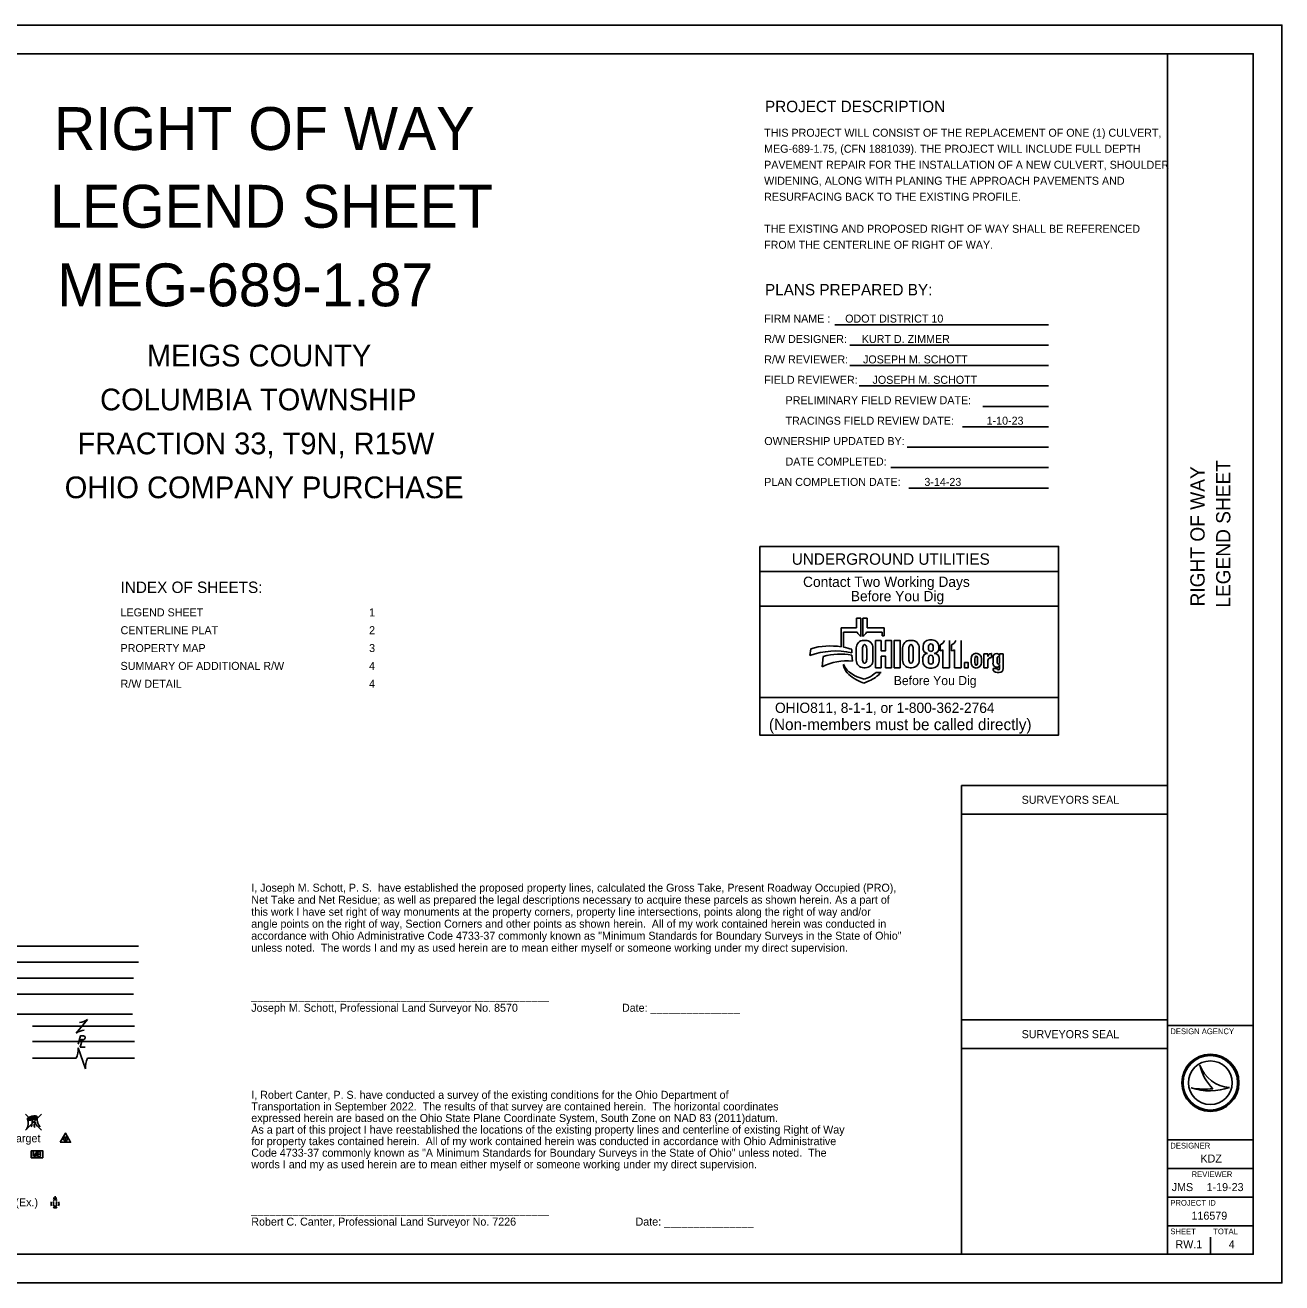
# Model space of a CAD drawing. Extents: x 0 to 34, y 0 to 22.
# Drawn here: x 12.02 to 34, y 0 to 22 of the extents above; entities that cross this region are included whole.
import ezdxf

# ---------------------------------------------------------------- set-up
doc = ezdxf.new("R2010")
doc.units = 0
for name, color, linetype in [('SH_Border', 7, 'Continuous'), ('SH_Cut_Line', 7, 'Continuous'), ('SH_Data', 7, 'Continuous'), ('SH_Text', 7, 'Continuous')]:
    doc.layers.add(name, color=color, linetype=linetype)

msp = doc.modelspace()

# ---------------------------------------------------------------- linework, layer by layer
at = {"layer": 'SH_Border'}
for p, q in [((32, 0.5), (32, 21.5)), ((32, 4.5), (33.5, 4.5)), ((32, 2.5), (33.5, 2.5)), ((32, 2), (33.5, 2)), ((32, 1.5), (33.5, 1.5)), ((32, 1), (33.5, 1))]:
    msp.add_line(p, q, dxfattribs=at)
msp.add_lwpolyline([(1.5, 21.5), (33.5, 21.5), (33.5, 0.5), (1.5, 0.5)], close=True, dxfattribs=at)
at = {"layer": 'SH_Cut_Line'}
msp.add_lwpolyline([(0, 0), (34, 0), (34, 22), (0, 22)], close=True, dxfattribs=at)
at = {"layer": 'SH_Data'}
for p, q in [((26.559, 11.46), (26.296, 11.46)), ((26.296, 11.46), (26.296, 11.125)), ((26.639, 11.626), (26.559, 11.626)), ((26.559, 11.626), (26.559, 11.46)), ((26.639, 11.309), (26.639, 11.626)), ((26.75, 11.626), (26.67, 11.626)), ((26.67, 11.626), (26.67, 11.309)), ((26.75, 11.46), (26.75, 11.626)), ((27.048, 11.46), (26.75, 11.46)), ((27.048, 11.319), (27.048, 11.46)), ((26.334, 11.119), (26.334, 11.383)), ((26.334, 11.383), (26.574, 11.383)), ((26.716, 11.238), (26.691, 11.238)), ((26.735, 11.383), (27.013, 11.383)), ((26.993, 11.237), (26.892, 11.237)), ((26.892, 11.237), (26.892, 10.759)), ((27.013, 11.383), (27.013, 11.319)), ((27.013, 11.319), (27.048, 11.319)), ((27.526, 11.238), (27.502, 11.238)), ((27.887, 11.245), (27.839, 11.245)), ((28.191, 11.237), (28.191, 10.759)), ((28.391, 11.237), (28.391, 10.759)), ((25.761, 11.091), (25.747, 10.974)), ((26.48, 11.023), (26.48, 11.081)), ((26.557, 11.105), (26.557, 10.893)), ((26.666, 10.91), (26.666, 11.092)), ((26.741, 11.092), (26.741, 10.91)), ((26.849, 10.893), (26.849, 11.105)), ((27.368, 11.105), (27.368, 10.893)), ((27.477, 10.91), (27.477, 11.092)), ((27.551, 11.092), (27.551, 10.91)), ((27.66, 10.893), (27.66, 11.105)), ((27.725, 11.131), (27.725, 11.095)), ((27.823, 11.078), (27.823, 11.136)), ((27.904, 11.136), (27.904, 11.078)), ((28.001, 11.095), (28.001, 11.131)), ((28.024, 11.057), (28.024, 11.158)), ((28.073, 10.759), (28.073, 11.071)), ((28.225, 11.057), (28.225, 11.158)), ((28.273, 10.759), (28.273, 11.071)), ((28.86, 11.002), (28.787, 11.002)), ((28.787, 11.002), (28.787, 10.759)), ((28.86, 10.955), (28.86, 11.002)), ((28.921, 11.01), (28.915, 11.01)), ((28.921, 10.936), (28.921, 11.01)), ((29.064, 10.957), (29.064, 11.004)), ((29.064, 11.004), (29.129, 11.004)), ((29.129, 11.004), (29.129, 10.745)), ((25.981, 10.956), (25.959, 10.776)), ((26.333, 10.819), (26.337, 10.792)), ((26.49, 10.873), (26.481, 10.979)), ((26.993, 10.759), (26.993, 10.961)), ((27.719, 10.925), (27.719, 10.874)), ((27.82, 10.865), (27.82, 10.926)), ((27.905, 10.926), (27.905, 10.865)), ((28.007, 10.874), (28.007, 10.925)), ((28.565, 10.85), (28.565, 10.918)), ((28.632, 10.849), (28.632, 10.918)), ((28.68, 10.918), (28.68, 10.849)), ((28.748, 10.918), (28.748, 10.85)), ((28.86, 10.759), (28.86, 10.886)), ((28.909, 10.936), (28.921, 10.936)), ((28.949, 10.837), (28.949, 10.941)), ((29.021, 10.851), (29.021, 10.927)), ((29.064, 10.927), (29.064, 10.851)), ((29.064, 10.745), (29.064, 10.815)), ((26.698, 10.558), (26.609, 10.589)), ((26.691, 10.759), (26.716, 10.759)), ((26.759, 10.585), (26.698, 10.558)), ((26.892, 10.759), (26.993, 10.759)), ((26.991, 10.679), (26.905, 10.679)), ((26.989, 10.676), (26.991, 10.679)), ((27.502, 10.759), (27.526, 10.759)), ((27.84, 10.753), (27.887, 10.753)), ((28.191, 10.759), (28.073, 10.759)), ((28.391, 10.759), (28.273, 10.759)), ((28.787, 10.759), (28.86, 10.759)), ((28.949, 10.745), (29.021, 10.745)), ((29.059, 10.676), (29.019, 10.676)), ((26.633, 10.512), (26.689, 10.488)), ((26.689, 10.488), (26.783, 10.529)), ((30.095, 9.581), (24.87, 9.581)), ((28.4, 8.2), (32, 8.2)), ((28.4, 4.1), (32, 4.1)), ((32.567, 3.81), (32.567, 3.81)), ((32.417, 3.41), (32.417, 3.41)), ((32.75, 3.5), (32.75, 3.5)), ((33.087, 3.419), (33.087, 3.419)), ((32.375, 0.675), (32.375, 0.675)), ((32.75, 0.5), (32.75, 0.8))]:
    msp.add_line(p, q, dxfattribs=at)
for points in [[(24.87, 12.881), (30.095, 12.881), (30.095, 12.441), (24.87, 12.441)], [(24.87, 12.441), (30.095, 12.441), (30.095, 11.836), (24.87, 11.836)], [(24.87, 11.836), (30.095, 11.836), (30.095, 10.241), (24.87, 10.241)], [(28.449, 10.849), (28.515, 10.849), (28.515, 10.759), (28.449, 10.759)], [(24.87, 10.241), (30.095, 10.241), (30.095, 9.581), (24.87, 9.581)], [(28.4, 8.7), (32, 8.7), (32, 4.6), (28.4, 4.6)], [(28.4, 4.6), (32, 4.6), (32, 0.5), (28.4, 0.5)]]:
    msp.add_lwpolyline(points, close=True, dxfattribs=at)
for points in [[(26.993, 10.961), (27.07, 10.961), (27.07, 10.759), (27.171, 10.759), (27.171, 11.237), (27.07, 11.237), (27.07, 11.057), (26.993, 11.057), (26.993, 11.237)], [(27.222, 10.759), (27.325, 10.759), (27.325, 11.237), (27.222, 11.237), (27.222, 10.759)], [(27.805, 11.011), (27.805, 11.011)], [(27.921, 11.011), (27.921, 11.011)]]:
    msp.add_lwpolyline(points, dxfattribs=at)
for radius in [0.5, 0.477, 0.477, 0.382]:
    msp.add_circle((32.75, 3.5), radius, dxfattribs=at)
for centre, radius, start, end in [((26.691, 11.105), 0.134, 90, 180), ((26.711, 11.438), 0.147, 201.9296, 240.7469), ((26.598, 11.438), 0.147, 299.2531, 338.0704), ((26.716, 11.105), 0.134, 0, 90), ((27.502, 11.105), 0.134, 90, 180), ((27.526, 11.105), 0.134, 0, 90), ((27.839, 11.131), 0.114, 90, 180), ((27.887, 11.131), 0.114, 0, 90), ((27.974, 11.281), 0.132, 292.5572, 340.7355), ((28.174, 11.281), 0.132, 292.5572, 340.7355), ((26.199, 9.721), 1.332, 77.8238, 109.8274), ((26.105, 9.917), 1.224, 81.0007, 106.3144), ((26.105, 9.917), 1.224, 72.1402, 79.2074), ((27.805, 10.925), 0.0865, 90, 180), ((27.808, 11.095), 0.0837, 180, 268.1442), ((27.918, 11.095), 0.0837, 272.2058, 0), ((27.921, 10.925), 0.0865, 0, 90), ((28.013, 11.188), 0.132, 275.1733, 297.0931), ((28.213, 11.188), 0.132, 275.1733, 297.0931), ((28.661, 10.918), 0.0956, 92.5886, 180), ((28.652, 10.918), 0.0956, 0, 87.4114), ((28.915, 10.955), 0.0548, 90, 180), ((29.018, 10.941), 0.0686, 92.6865, 180), ((29.012, 10.957), 0.0524, 0, 86.9262), ((26.388, 9.929), 0.95, 83.8248, 116.8021), ((26.28, 9.904), 1.094, 79.44, 105.8467), ((26.613, 10.927), 0.3, 201.0457, 232.5314), ((26.548, 10.828), 0.214, 189.6817, 216.0884), ((26.691, 10.893), 0.134, 180, 270), ((26.716, 10.893), 0.134, 270, 0), ((27.502, 10.893), 0.134, 180, 270), ((27.526, 10.893), 0.134, 270, 0), ((27.84, 10.874), 0.121, 180, 270), ((27.887, 10.874), 0.121, 270, 0), ((28.661, 10.85), 0.0956, 180, 267.4114), ((28.652, 10.85), 0.0956, 272.5886, 0), ((28.909, 10.886), 0.0493, 90, 180), ((29.018, 10.837), 0.0692, 180, 265.7132), ((29.017, 10.815), 0.0467, 264.7825, 0), ((26.748, 10.974), 0.461, 216.0884, 235.7167), ((26.9, 11.302), 0.773, 232.5314, 241.794), ((26.997, 11.339), 0.903, 235.7167, 246.2325), ((26.773, 11.065), 0.504, 241.794, 250.9821), ((26.545, 11.078), 0.538, 293.4582, 312.0712), ((26.545, 11.078), 0.599, 293.4582, 317.8286), ((29.019, 10.745), 0.0699, 180, 270), ((29.059, 10.745), 0.0699, 270, 0), ((33.116, 3.998), 0.58, 198.9257, 198.9319), ((33.347, 3.97), 0.796, 191.6379, 191.6421), ((33.116, 3.998), 0.58, 198.9319, 267.1657), ((33.347, 3.97), 0.796, 191.6421, 226.0947), ((32.739, 4.37), 1.013, 251.4576, 290.0832), ((32.648, 4.654), 1.266, 259.4964, 259.4995), ((32.739, 4.37), 1.013, 251.4527, 251.4576), ((32.648, 4.654), 1.266, 259.4995, 276.6672)]:
    msp.add_arc(centre, radius, start, end, dxfattribs=at)
for centre, major_axis, ratio, start_param, end_param in [((26.703, 11.092), (0, 0.0723), 0.514403, 4.712389, 7.853982), ((27.514, 11.092), (0, 0.0723), 0.514403, 4.712389, 7.853982), ((27.864, 11.136), (0.0404, 0), 0.969373, 0, 3.141593), ((27.864, 11.078), (0.0404, 0), 0.818453, 3.141593, 6.283185), ((26.703, 10.91), (0, 0.0723), 0.514403, 1.570796, 4.712389), ((27.514, 10.91), (0, 0.0723), 0.514403, 1.570796, 4.712389), ((27.862, 10.926), (0, 0.0535), 0.794529, 4.712389, 7.853982), ((27.862, 10.865), (0.0425, 0), 0.959837, 3.141593, 6.283185), ((28.656, 10.918), (0, 0.0434), 0.553236, 4.712389, 7.853982), ((28.656, 10.849), (0, 0.046), 0.522014, 1.570796, 4.712389), ((29.043, 10.927), (0, 0.0275), 0.777179, 4.712389, 7.853982), ((29.043, 10.851), (0, 0.0275), 0.777179, 1.570796, 4.712389), ((29.043, 10.745), (0.0214, 0), 0.959012, 3.141593, 6.283185)]:
    msp.add_ellipse(centre, major_axis=major_axis, ratio=ratio, start_param=start_param, end_param=end_param, dxfattribs=at)
at = {"layer": 'SH_Text'}
for p, q in [((26.181, 16.76), (29.918, 16.76)), ((26.445, 16.403), (29.918, 16.403)), ((26.445, 16.046), (29.918, 16.046)), ((26.609, 15.689), (29.918, 15.689)), ((28.773, 15.331), (29.918, 15.331)), ((28.415, 14.974), (29.918, 14.974)), ((27.445, 14.617), (29.918, 14.617)), ((27.16, 14.26), (29.918, 14.26)), ((27.475, 13.903), (29.918, 13.903)), ((10.521, 5.889), (14.004, 5.889)), ((10.521, 5.609), (14.004, 5.609)), ((10.02, 5.329), (13.92, 5.329)), ((10.02, 5.049), (13.92, 5.049)), ((9.553, 4.699), (13.903, 4.698)), ((12.151, 4.489), (13.933, 4.489)), ((12.916, 4.369), (13.116, 4.609)), ((13.016, 4.489), (13.016, 4.489)), ((12.151, 4.224), (13.933, 4.224)), ((12.974, 4.253), (13.039, 4.253)), ((13.014, 4.222), (13.014, 4.222)), ((12.951, 4.113), (13.081, 3.744)), ((12.151, 3.929), (12.916, 3.929)), ((13.016, 3.929), (13.016, 3.929)), ((13.116, 3.929), (13.933, 3.929)), ((12.029, 2.948), (12.307, 2.669)), ((12.307, 2.948), (12.029, 2.669)), ((12.168, 2.809), (12.168, 2.809)), ((12.168, 2.809), (12.168, 2.809)), ((12.23, 2.249), (12.23, 2.249)), ((12.579, 1.484), (12.515, 1.484)), ((12.52, 1.425), (12.52, 1.356)), ((12.547, 1.452), (12.547, 1.516)), ((12.547, 1.382), (12.547, 1.382)), ((12.574, 1.425), (12.574, 1.356))]:
    msp.add_line(p, q, dxfattribs=at)
for points in [[(12.953, 4.174), (12.992, 4.322), (13.043, 4.322)], [(13.027, 4.27), (12.988, 4.122), (13.075, 4.122)], [(12.165, 2.209), (12.165, 2.289), (12.194, 2.209), (12.221, 2.289), (12.221, 2.209)], [(12.281, 2.252), (12.284, 2.255), (12.286, 2.257), (12.287, 2.259), (12.288, 2.26), (12.289, 2.263), (12.289, 2.265), (12.291, 2.269), (12.291, 2.271), (12.291, 2.273), (12.29, 2.277), (12.289, 2.28), (12.287, 2.283), (12.284, 2.285), (12.281, 2.287), (12.28, 2.287), (12.277, 2.289), (12.246, 2.289), (12.246, 2.209), (12.281, 2.209), (12.285, 2.211), (12.289, 2.214), (12.292, 2.219), (12.294, 2.225), (12.295, 2.231), (12.295, 2.234), (12.293, 2.238), (12.291, 2.244), (12.288, 2.248), (12.281, 2.252), (12.246, 2.252)]]:
    msp.add_lwpolyline(points, dxfattribs=at)
for points in [[(12.638, 2.459), (12.818, 2.459), (12.728, 2.62)], [(12.13, 2.31), (12.33, 2.31), (12.33, 2.187), (12.13, 2.187)]]:
    msp.add_lwpolyline(points, close=True, dxfattribs=at)
for radius in [0.035, 0.008]:
    msp.add_circle((12.728, 2.516), radius, dxfattribs=at)
for centre, radius, start, end in [((13.074, 4.154), 0.267, 93.6945, 126.337), ((12.958, 4.823), 0.267, 273.6945, 306.337), ((13.038, 4.288), 0.0345, 270.471, 81.3281), ((12.619, 4.08), 0.334, 332.9422, 5.5848), ((13.413, 3.777), 0.334, 152.9422, 185.5848), ((11.877, 2.791), 0.2, 331.5338, 20.9269), ((12.449, 2.866), 0.215, 171.4106, 219.9194), ((11.892, 2.81), 0.253, 340.7938, 3.5481), ((12.364, 2.769), 0.182, 178.7926, 197.1224), ((12.494, 2.911), 0.316, 194.9653, 212.1216), ((12.547, 1.382), 0.07, 150.0184, 209.9816), ((12.547, 1.382), 0.07, 60.0184, 120.0157), ((12.547, 1.382), 0.07, 239.9843, 299.9816), ((12.547, 1.369), 0.03, 205.1924, 334.8076), ((12.547, 1.382), 0.07, 330.0184, 29.9816)]:
    msp.add_arc(centre, radius, start, end, dxfattribs=at)
for major_axis in [(0.0868, 0.0187), (0.0651, 0.0141), (0.0488, 0.0105), (0.0275, 0.0059), (0.0154, 0.0033)]:
    msp.add_ellipse((12.15, 2.884), major_axis=major_axis, ratio=0.36865, dxfattribs=at)

# ---------------------------------------------------------------- texts
at = {"layer": 'SH_Data'}
for s, height, p in [('RIGHT OF WAY', 0.75, (12.527, 19.816)), ('LEGEND SHEET', 0.75, (12.458, 18.457)), ('MEG-689-1.87', 0.75, (12.583, 17.082)), ('MEIGS COUNTY', 0.38, (14.152, 16.03)), ('COLUMBIA TOWNSHIP', 0.38, (13.334, 15.262)), ('FRACTION 33, T9N, R15W', 0.38, (12.94, 14.493)), ('OHIO COMPANY PURCHASE', 0.38, (12.715, 13.725)), ('UNDERGROUND UTILITIES', 0.2, (25.43, 12.561)), ('Contact Two Working Days', 0.18, (25.627, 12.173)), ('INDEX OF SHEETS:', 0.2, (13.692, 12.067)), ('Before You Dig', 0.18, (26.462, 11.923)), ('LEGEND SHEET', 0.14, (13.692, 11.658)), ('1', 0.14, (18.038, 11.658)), ('CENTERLINE PLAT', 0.14, (13.692, 11.346)), ('2', 0.14, (18.038, 11.346)), ('PROPERTY MAP', 0.14, (13.692, 11.034)), ('3', 0.14, (18.038, 11.034)), ('SUMMARY OF ADDITIONAL R/W', 0.14, (13.692, 10.722)), ('4', 0.14, (18.038, 10.722)), ('Before You Dig', 0.15972, (27.213, 10.456)), ('R/W DETAIL', 0.14, (13.692, 10.41)), ('4', 0.14, (18.038, 10.41)), ('OHIO811, 8-1-1, or 1-800-362-2764', 0.18, (25.136, 9.969)), ('(Non-members must be called directly)', 0.2, (25.03, 9.668)), ('SURVEYORS SEAL', 0.14, (29.45, 8.38)), ('SURVEYORS SEAL', 0.14, (29.45, 4.28)), ('DESIGN AGENCY', 0.1, (32.05, 4.35)), ('DESIGNER', 0.1, (32.05, 2.35)), ('KDZ', 0.14, (32.577, 2.105)), ('REVIEWER', 0.1, (32.422, 1.85)), ('JMS', 0.14, (32.074, 1.605)), ('1-19-23', 0.14, (32.685, 1.605)), ('PROJECT ID', 0.1, (32.05, 1.35)), ('116579', 0.14, (32.42, 1.105)), ('SHEET', 0.1, (32.05, 0.85)), ('TOTAL', 0.1, (32.8, 0.85)), ('RW.1', 0.14, (32.14, 0.605)), ('4', 0.14, (33.072, 0.605))]:
    msp.add_text(s, height=height, dxfattribs=at).set_placement(p)
for s, p in [('LEGEND SHEET', (33.1, 11.81)), ('RIGHT OF WAY', (32.65, 11.832))]:
    msp.add_text(s, height=0.25, rotation=90, dxfattribs=at).set_placement(p)
at = {"layer": 'SH_Text'}
for s, height, p in [('PROJECT DESCRIPTION', 0.2, (24.961, 20.478)), ('THIS PROJECT WILL CONSIST OF THE REPLACEMENT OF ONE (1) CULVERT, ', 0.14, (24.946, 20.048)), ('MEG-689-1.75, (CFN 1881039). THE PROJECT WILL INCLUDE FULL DEPTH ', 0.14, (24.946, 19.768)), ('PAVEMENT REPAIR FOR THE INSTALLATION OF A NEW CULVERT, SHOULDER ', 0.14, (24.946, 19.488)), ('WIDENING, ALONG WITH PLANING THE APPROACH PAVEMENTS AND ', 0.14, (24.946, 19.208)), ('RESURFACING BACK TO THE EXISTING PROFILE.', 0.14, (24.946, 18.928)), ('THE EXISTING AND PROPOSED RIGHT OF WAY SHALL BE REFERENCED ', 0.14, (24.946, 18.368)), ('FROM THE CENTERLINE OF RIGHT OF WAY.', 0.14, (24.946, 18.088)), ('PLANS PREPARED BY:', 0.2, (24.961, 17.273)), ('FIRM NAME :     ODOT DISTRICT 10', 0.14, (24.949, 16.797)), ('R/W DESIGNER:     KURT D. ZIMMER', 0.14, (24.949, 16.44)), ('R/W REVIEWER:     JOSEPH M. SCHOTT', 0.14, (24.949, 16.083)), ('FIELD REVIEWER:     JOSEPH M. SCHOTT', 0.14, (24.949, 15.726)), ('PRELIMINARY FIELD REVIEW DATE:', 0.14, (25.321, 15.369)), ('TRACINGS FIELD REVIEW DATE:           1-10-23', 0.14, (25.321, 15.011)), ('OWNERSHIP UPDATED BY:', 0.14, (24.949, 14.655)), ('DATE COMPLETED:', 0.14, (25.321, 14.297)), ('PLAN COMPLETION DATE:', 0.14, (24.949, 13.94)), ('3-14-23', 0.14, (27.749, 13.94)), ('I, Joseph M. Schott, P. S.  have established the proposed property lines, calculated the Gross Take, Present Roadway Occupied (PRO),', 0.14, (15.978, 6.842)), ('Net Take and Net Residue; as well as prepared the legal descriptions necessary to acquire these parcels as shown herein. As a part of', 0.14, (15.978, 6.632)), ('this work I have set right of way monuments at the property corners, property line intersections, points along the right of way and/or', 0.14, (15.978, 6.422)), ('angle points on the right of way, Section Corners and other points as shown herein.  All of my work contained herein was conducted in', 0.14, (15.978, 6.212)), ('accordance with Ohio Administrative Code 4733-37 commonly known as "Minimum Standards for Boundary Surveys in the State of Ohio"', 0.14, (15.978, 6.002)), ('unless noted.  The words I and my as used herein are to mean either myself or someone working under my direct supervision.', 0.14, (15.978, 5.792)), ('__________________________________________________', 0.14, (15.978, 4.952)), ('Joseph M. Schott, Professional Land Surveyor No. 8570                                   Date: _______________                  ', 0.14, (15.978, 4.742)), ('I, Robert Canter, P. S. have conducted a survey of the existing conditions for the Ohio Department of', 0.14, (15.978, 3.219)), ('Transportation in September 2022.  The results of that survey are contained herein.  The horizontal coordinates', 0.14, (15.978, 3.016)), ('expressed herein are based on the Ohio State Plane Coordinate System, South Zone on NAD 83 (2011)datum.', 0.14, (15.978, 2.814)), ('As a part of this project I have reestablished the locations of the existing property lines and centerline of existing Right of Way ', 0.14, (15.978, 2.611)), ('Wetland (Pr)         , Grass (Pr)            , Aerial Target    ', 0.14, (8.004, 2.459)), ('for property takes contained herein.  All of my work contained herein was conducted in accordance with Ohio Administrative ', 0.14, (15.978, 2.409)), ('Code 4733-37 commonly known as "A Minimum Standards for Boundary Surveys in the State of Ohio" unless noted.  The ', 0.14, (15.978, 2.206)), ('words I and my as used herein are to mean either myself or someone working under my direct supervision.', 0.14, (15.978, 2.004)), ('Water Valve (Ex)         , Utility Valve Unknown (Ex.)', 0.14, (8.004, 1.339)), ('__________________________________________________', 0.14, (15.978, 1.211)), ('Robert C. Canter, Professional Land Surveyor No. 7226                           ', 0.14, (15.978, 1.001)), ('Date: _______________ ', 0.14, (22.698, 1.001))]:
    msp.add_text(s, height=height, dxfattribs=at).set_placement(p)

doc.saveas('drawing.dxf')
